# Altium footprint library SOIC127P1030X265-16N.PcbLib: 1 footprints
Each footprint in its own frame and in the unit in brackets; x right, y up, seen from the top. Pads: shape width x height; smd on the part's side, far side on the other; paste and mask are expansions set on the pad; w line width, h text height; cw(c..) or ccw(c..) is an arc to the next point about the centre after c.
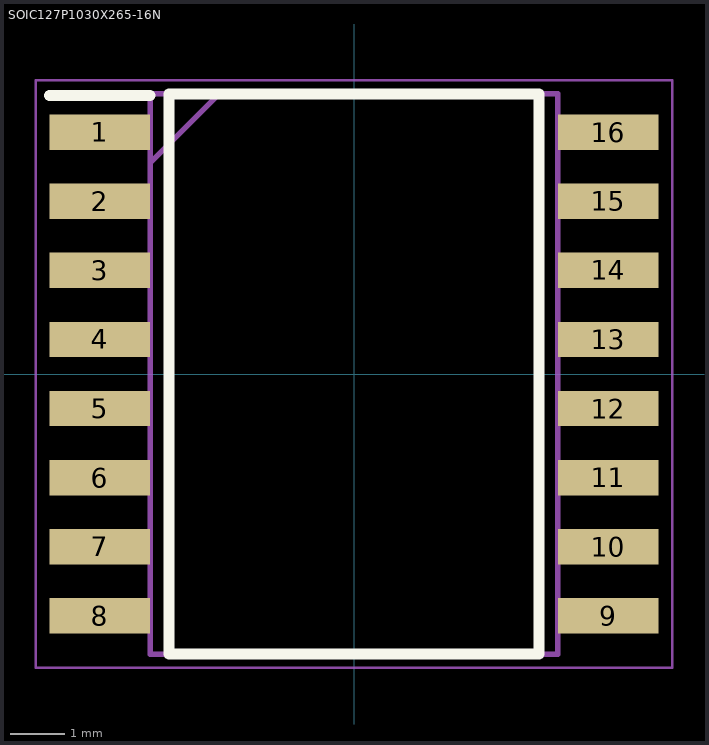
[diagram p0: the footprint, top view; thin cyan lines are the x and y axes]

## SOIC127P1030X265-16N [mm]
pads (16):
  rect 1.85x0.65 smd: 1(-4.675,4.445) 2(-4.675,3.175) 3(-4.675,1.905) 4(-4.675,0.635) 5(-4.675,-0.635) 6(-4.675,-1.905) 7(-4.675,-3.175) 8(-4.675,-4.445) 9(4.675,-4.445) 10(4.675,-3.175) 11(4.675,-1.905) 12(4.675,-0.635) 13(4.675,0.635) 14(4.675,1.905) 15(4.675,3.175) 16(4.675,4.445)
Top Overlay:
  lines w0.2: -5.6,5.12 -3.75,5.12 ; -3.4,-5.15 3.4,-5.15 3.4,5.15 -3.4,5.15 -3.4,-5.15
Mechanical 15:
  lines w0.1: -3.75,3.88 -2.48,5.15 ; -3.75,-5.15 3.75,-5.15 3.75,5.15 -3.75,5.15 -3.75,-5.15
Mechanical 20:
  lines w0.05: -5.85,-5.4 5.85,-5.4 5.85,5.4 -5.85,5.4 -5.85,-5.4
